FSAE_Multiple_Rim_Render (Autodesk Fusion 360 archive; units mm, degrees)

design "FSAE Multiple Rim Render" references "FSAE Rim"
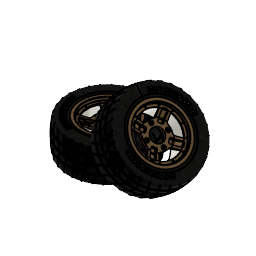
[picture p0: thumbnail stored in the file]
part number: 2026-08-31-14-58-38-211
component_insert "Component Insert1"
component_insert "Component Insert2"

design "FSAE Rim" references "Hexagon Nut DIN 934 - M4 x 0.7 Steel 6 Plain", "Hexagon Socket Head Cap Screw DIN 912 - M4 x 0.7 x 16 Steel 4.6 Plain"
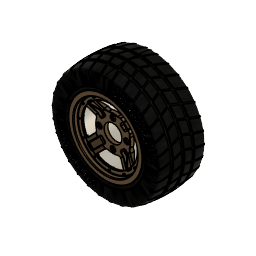
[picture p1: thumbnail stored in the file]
part number: 2026-07-27-09-56-27-671
part number: 2026-08-04-10-59-52-273
part number: 2026-08-04-10-59-52-284
part number: 2026-08-04-10-59-52-289
sketch "Sketch1" plane through (0, 0, 0) normal (1, 0, 0) x axis (0, 1, 0)
  line L1 (153.5, 0) -> (0, 0)
  line L2 (0, 119.5) -> (0, 104)
  line L3 (143.5, 124.5) -> (5, 124.5)
  line L4 (148.5, 134.75) -> (148.5, 129.5)
  line L5 (153.5, 138.25) -> (152, 138.25)
  line L6 (2.5, 119.5) -> (2.5, 104)
  line L7 (143.5, 122) -> (5, 122)
  line L8 (151, 134.75) -> (151, 129.5)
  line L9 (153.5, 135.75) -> (152, 135.75)
  line L10 (2.5, 104) -> (0, 104)
  line L11 (153.5, 135.75) -> (153.5, 138.25)
  arc A1 centre (152, 134.75) radius 3.5 clockwise from (148.5, 134.75) to (152, 138.25)
  arc A2 centre (143.5, 129.5) radius 5 clockwise from (148.5, 129.5) to (143.5, 124.5)
  arc A3 centre (5, 119.5) radius 5 clockwise from (0, 119.5) to (5, 124.5)
  arc A4 centre (5, 119.5) radius 2.5 clockwise from (2.5, 119.5) to (5, 122)
  arc A5 centre (143.5, 129.5) radius 7.5 clockwise from (151, 129.5) to (143.5, 122)
  arc A6 centre (152, 134.75) radius 1 clockwise from (151, 134.75) to (152, 135.75)
  point P1 (0, 0)
  point P2 (0, 0)
  point P4 (0, 104)
  point P3 (153.5, 0)
  point P7 (153.5, 138.25)
  point P6 (148.5, 124.5)
  point P5 (0, 124.5)
  coincident P1 P2
  horizontal L1
  perpendicular L1 L2
  perpendicular L2 L3
  perpendicular L3 L4
  perpendicular L4 L5
  vertical P1 P4
  vertical P3 P7
  tangent L4 A1
  tangent L5 A1
  coincident P6 L3
  coincident P6 L4
  tangent L3 A2
  tangent L4 A2
  coincident P5 L2
  coincident P5 L3
  tangent L2 A3
  tangent L3 A3
  equal A2 A3
  perpendicular L6 L10
  perpendicular L9 L11
  dimension "d1" distance P2 P3 = 153.5
  dimension "d2" = 208
  dimension "d3" = 249
  dimension "d4" = 276.5
  dimension "d5" distance P5 P6 = 148.5
  dimension "d6" radius A1 = 3.5
  dimension "d7" radius A2 = 5
  dimension "d8" = 2.5
revolve "Revolve1" sketch "Sketch1" AlongAngle 360 bodies "FSAE Rim Back"
sketch "Sketch2" plane through (0, 0, 0) normal (0, -1, 0) x axis (1, 0, 0)
  circle C1 centre (0, 0) radius 104
  circle C2 centre (0, 0) radius 119.5
  circle C3 centre (0, 0) radius 112
  circle C4 centre (0, 112) radius 2.15
  point P1 (0, 0)
  point P3 (0, 0)
  point P4 (0, 112)
  coincident P1 P3
  coincident C3 P4
  vertical P3 P4
  dimension "d10" diameter C3 = 224
  dimension "d11" diameter C4 = 4.3
extrude "Extrude1" cut sketch "Sketch2" profile of C4 to an object
circular_pattern "C-Pattern1" TotalAngle 360
canvas "Canvas1"
move "Move1"
sketch "Sketch4" plane through (0, 0, 0) normal (1, 0, 0) x axis (0, 1, 0)
  line L1 (14, 0) -> (0, 0)
  line L2 (14, 72.5) -> (14, 0)
  line L3 (-8, 102.5) -> (14, 72.5)
  line L4 (-8, 124.5) -> (-8, 102.5)
  line L5 (-23.5, 124.5) -> (-8, 124.5)
  line L6 (-23.5, 138) -> (-23.5, 124.5)
  line L7 (-28.25, 138) -> (-23.5, 138)
  line L8 (-28.25, 0) -> (-28.25, 138)
  line L9 (0, 0) -> (-28.25, 0)
  line L10 (-13, 118.1658) -> (-28.25, 119.5)
  line L11 (-13, 102.5) -> (-13, 118.1658)
  line L12 (0, 68.6338) -> (-13, 102.5)
  line L13 (0, 0) -> (0, 68.6338)
  point P1 (0, 0)
  point P2 (0, 0)
  point P11 (0, 0)
  point P12 (-28.25, 119.5)
  point P5 (-8, 102.5)
  point P14 (-13, 102.5)
  point P3 (14, 0)
  point P4 (14, 72.5)
  point P6 (-8, 124.5)
  point P8 (-23.5, 138)
  point P9 (-28.25, 138)
  coincident P1 P2
  horizontal L1
  perpendicular L1 L2
  perpendicular L1 L4
  perpendicular L4 L5
  perpendicular L5 L6
  perpendicular L6 L7
  coincident P1 P11
  collinear L1 L9
  perpendicular L8 L9
  coincident L8 P12
  parallel L8 L11
  vertical L13
  horizontal P5 P14
  dimension "d29" distance P2 P3 = 14
  dimension "d30" = 145
  dimension "d31" = 205
  dimension "d32" = 249
  dimension "d33" = 276
  dimension "d34" distance P4 P6 = 22
  dimension "d35" distance P6 P8 = 15.5
  dimension "d36" distance P8 P9 = 4.75
  dimension "d37" distance L4 L11 = 5
  dimension "d38" angle L12 L13 = 159
  dimension "d39" angle L10 L11 = 95
  dimension "d40" = 239
revolve "Revolve3" sketch "Sketch4" AlongAngle 360 bodies "FSAE Rim Front"
sketch "Sketch5" plane through (0, 0, 0) normal (0, -1, 0) x axis (1, 0, 0)
  circle C1 centre (0, 0) radius 68.6338
  circle C2 centre (0, 0) radius 33
  point P1 (0, 0)
  point P3 (0, 0)
  coincident P1 P3
  dimension "d42" diameter C2 = 66
extrude "Extrude2" cut sketch "Sketch5" profile of C2 to an object
sketch "Sketch6" plane through (0, 0, 0) normal (0, -1, 0) x axis (1, 0, 0)
  circle C1 centre (0, 0) radius 33
  circle C2 centre (0, 0) radius 68.6338
  circle C3 centre (0, 0) radius 50.8
  point P1 (0, 0)
  point P4 (0, 0)
  point P3 (0, 50.8)
  coincident P1 P4
  coincident P3 C3
  vertical P1 P3
  dimension "d45" diameter C3 = 101.6
hole "Hole1" HoleDiameter 10.5 TipAngle 180 CBDepth 5 CBDiameter 20
chamfer "Chamfer2" sketch "Sketch1" distance 0.5
circular_pattern "C-Pattern2" TotalAngle 360
sketch "Sketch7" plane through (0, -13, 0) normal (0, -1, 0) x axis (1, 0, 0)
  circle C1 centre (0, 0) radius 102.5
  circle C2 centre (0, 0) radius 118.1658
  circle C3 centre (0, 0) radius 112
  point P1 (0, 0)
  point P3 (0, 0)
  point P4 (0, 112)
  coincident P1 P3
  coincident C3 P4
  vertical P1 P4
  dimension "d53" diameter C3 = 224
hole "Hole2" HoleDiameter 4.3 TipAngle 180
circular_pattern "C-Pattern3" TotalAngle 360
fillet "Fillet1" radius 1 3 2
chamfer "Chamfer1" distance 0.5
form "Form1" bodies "Tire"
fillet "Fillet2" radius 5
sketch "Sketch8" plane through (0, 0, 0) normal (1, 0, 0) x axis (0, 1, 0)
  line L1 (47.5, 224.911) -> (47.5, 204.911)
  line L2 (57.5, 224.911) -> (47.5, 224.911)
  line L3 (57.5, 204.9943) -> (57.5, 224.911)
  line L4 (87.5, 224.911) -> (87.5, 204.2438)
  line L5 (97.5, 224.911) -> (87.5, 224.911)
  line L6 (97.5, 203.6595) -> (97.5, 224.911)
  line L7 (17.5, 224.911) -> (17.5, 203.6595)
  line L8 (7.5, 224.911) -> (17.5, 224.911)
  line L9 (7.5, 202.9073) -> (7.5, 224.911)
  arc A1 centre (57.5, -395.0057) radius 600 clockwise from (-46, 196) to (161, 196)
  point P2 (-46, 196)
  point P3 (161, 196)
  point P8 (57.5, 204.9943)
  point P9 (87.5, 204.2438)
  point P12 (97.5, 203.6595)
  point P13 (17.5, 203.6595)
  point P16 (7.5, 202.9073)
  point P5 (47.5, 204.911)
  point P1 (0, 0)
  point P6 (47.5, 224.911)
  point P7 (57.5, 224.911)
  horizontal P2 P3
  vertical L1
  perpendicular L1 L2
  midpoint A1 P8
  perpendicular L2 L3
  coincident A1 P9
  parallel L3 L4
  perpendicular L4 L5
  coincident A1 P12
  perpendicular L5 L6
  coincident A1 P13
  perpendicular L5 L7
  perpendicular L7 L8
  coincident A1 P16
  perpendicular L8 L9
  collinear L2 L8
  collinear L2 L5
  equal L2 L8
  equal L2 L5
  coincident A1 P5
  dimension "d68" radius A1 = 600
  dimension "d69" distance P1 P3 = 196
  dimension "d70" distance P1 P2 = 46
  dimension "d71" distance P1 P3 = 161
  dimension "d73" distance P6 P7 = 10
  dimension "d74" distance L1 L7 = 30
  dimension "d75" distance L3 L4 = 30
  dimension "d76" distance P5 P6 = 20
revolve "Revolve4" AlongAngle 360
revolve "Revolve5" sketch "Sketch8" AlongAngle 360
work_plane "WorkPlane1" AlongDistance 275 ExtraOffset 0
sketch "Sketch9" plane through (0, 0, 275) normal (0, 0, 1) x axis (1, 0, 0)
  line L1 (-48.7008, 53.5011) -> (0, -75.7953)
  line L2 (0, 197.5142) -> (-48.7008, 53.5011)
  line L3 (-43.392, 53.5917) -> (4.6791, -74.0329)
  line L4 (4.7365, 195.9124) -> (-43.392, 53.5917)
  line L5 (4.6791, -74.0329) -> (0, -75.7953)
  line L6 (0, 197.5142) -> (4.7365, 195.9124)
  perpendicular L3 L5
  perpendicular L2 L6
  dimension "d80" = 5
step "SurfaceExtend" extendDistance 125
extrude "Extrude3" cut sketch "Sketch9" to an object
circular_pattern "C-Pattern4" countU 30 TotalAngle 360
remove_body "RemoveBody1"
remove_body "RemoveBody2"
work_plane "WorkPlane2" AlongDistance -150 ExtraOffset 0
sketch "Sketch10" plane through (0, -150, 0) normal (0, 1, 0) x axis (1, 0, 0)
  circle C1 centre (0, 0) radius 157.5
  point P1 (0, 0)
  point P2 (0, 0)
  coincident P1 P2
  dimension "d88" diameter C1 = 315
  dimension "d89" Text1-Height = 20
extrude "Extrude4" sketch "Sketch10" blind 2
circular_pattern "C-Pattern5" TotalAngle 360
component_from_bodies "Body->Comp1"
component_from_bodies "Body->Comp2"
component_from_bodies "Body->Comp3"
sketch "Sketch1" plane through (0, -13, 0) normal (0, -1, 0) x axis (1, 0, 0)
  line L1 (0, 103.056) -> (0, 0)
  line L2 (103.056, 0) -> (0, 0)
  line L3 (72.8716, 72.8716) -> (0, 0)
  line L4 (88.3726, 53.0172) -> (60.1041, 24.7487)
  line L5 (53.0172, 88.3726) -> (24.7487, 60.1041)
  circle C1 centre (0, 0) radius 103.056
  circle C2 centre (0, 112) radius 2.15
  circle C3 centre (56, 96.9948) radius 2.15
  circle C4 centre (96.9948, 56) radius 2.15
  circle C5 centre (112, 0) radius 2.15
  circle C6 centre (96.9948, -56) radius 2.15
  circle C7 centre (56, -96.9948) radius 2.15
  circle C8 centre (0, -112) radius 2.15
  circle C9 centre (-56, -96.9948) radius 2.15
  circle C10 centre (-96.9948, -56) radius 2.15
  circle C11 centre (-112, 0) radius 2.15
  circle C12 centre (-96.9948, 56) radius 2.15
  circle C13 centre (-56, 96.9948) radius 2.15
  circle C14 centre (0, 0) radius 116.3331
  arc A1 centre (0, 0) radius 65 clockwise from (0, 65) to (65, 0)
  arc A2 centre (0, 0) radius 65 clockwise from (65, 0) to (0, 65)
  point P2 (0, 0)
  point P16 (0, 0)
  point P17 (0, 103.056)
  point P18 (103.056, 0)
  point P15 (0, 0)
  point P19 (0, 0)
  point P20 (72.8716, 72.8716)
  point P22 (24.7487, 60.1041)
  point P21 (60.1041, 24.7487)
  point P23 (53.0172, 88.3726)
  point P24 (88.3726, 53.0172)
  point P25 (0, 65)
  point P26 (65, 0)
  concentric C1 A1
  coincident P2 P16
  coincident C1 P17
  vertical L1
  coincident C1 P18
  perpendicular L1 L2
  coincident P15 P19
  coincident C1 P20
  coincident P22 A1
  coincident P21 A1
  coincident C1 P23
  coincident C1 P24
  coincident L1 P25
  coincident L2 P26
  concentric A1 A2
  dimension "d95" diameter A1 = 130
  dimension "d96" angle L1 L3 = 45
extrude "Extrude1" cut sketch "Sketch1" profile of C1 L1 L2 L4 L5 A1 to an object
circular_pattern "C-Pattern1" TotalAngle 360
sketch "Sketch2" plane through (0, -13, 0) normal (0, -1, 0) x axis (1, 0, 0)
  line L1 (72.8716, 72.8716) -> (0, 0)
  line L2 (65.9862, 82.9568) -> (25.8367, 42.8073)
  line L3 (82.9568, 65.9862) -> (42.8073, 25.8367)
  arc A1 centre (0, 0) radius 103.056 clockwise from (-53.0172, 88.3726) to (53.0172, 88.3726)
  arc A2 centre (0, 0) radius 103.056 clockwise from (53.0172, 88.3726) to (88.3726, 53.0172)
  arc A3 centre (0, 0) radius 103.056 clockwise from (88.3726, 53.0172) to (88.3726, -53.0172)
  arc A4 centre (0, 0) radius 103.056 clockwise from (88.3726, -53.0172) to (53.0172, -88.3726)
  arc A5 centre (0, 0) radius 103.056 clockwise from (53.0172, -88.3726) to (-53.0172, -88.3726)
  arc A6 centre (0, 0) radius 103.056 clockwise from (-53.0172, -88.3726) to (-88.3726, -53.0172)
  arc A7 centre (0, 0) radius 103.056 clockwise from (-88.3726, -53.0172) to (-88.3726, 53.0172)
  arc A8 centre (0, 0) radius 103.056 clockwise from (-88.3726, 53.0172) to (-53.0172, 88.3726)
  circle C1 centre (0, 112) radius 2.15
  circle C2 centre (56, 96.9948) radius 2.15
  circle C3 centre (96.9948, 56) radius 2.15
  circle C4 centre (112, 0) radius 2.15
  circle C5 centre (96.9948, -56) radius 2.15
  circle C6 centre (56, -96.9948) radius 2.15
  circle C7 centre (0, -112) radius 2.15
  circle C8 centre (-56, -96.9948) radius 2.15
  circle C9 centre (-96.9948, -56) radius 2.15
  circle C10 centre (-112, 0) radius 2.15
  circle C11 centre (-96.9948, 56) radius 2.15
  circle C12 centre (-56, 96.9948) radius 2.15
  circle C13 centre (0, 0) radius 116.3331
  circle C14 centre (0, 0) radius 50
  circle C15 centre (0, 0) radius 106
  point P23 (0, 0)
  point P25 (0, 0)
  point P27 (25.8367, 42.8073)
  point P28 (42.8073, 25.8367)
  point P29 (82.9568, 65.9862)
  point P30 (65.9862, 82.9568)
  parallel L1 L2
  parallel L1 L3
  coincident P23 P25
  concentric C14 C15
  coincident C14 P27
  coincident C14 P28
  coincident C15 P29
  coincident C15 P30
  dimension "d103" distance L1 L2 = 12
  dimension "d104" distance L1 L3 = 12 (= "d103")
  dimension "d105" diameter C14 = 100
  dimension "d106" diameter C15 = 212
extrude "Extrude2" cut sketch "Sketch2" profile of A2 L2 L3 C14 C15 to an object offset 2
fillet "Fillet1" radius 5
fillet "Fillet2" radius 10
fillet "Fillet3" radius 2
circular_pattern "C-Pattern2" TotalAngle 360
fillet "Fillet4" radius 15 5
chamfer "Chamfer1" sketch "Sketch1" distance 1
step "Screw1"
joint "Assemble" alignAngle 0 alignOffsetX 0 alignOffsetY 0 alignOffsetZ 0
step "Screw2"
joint "Assemble" alignAngle 0 alignOffsetX 0 alignOffsetY 0 alignOffsetZ 0
step "Screw3"
joint "Assemble" alignAngle 0 alignOffsetX 0 alignOffsetY 0 alignOffsetZ 0
step "Screw4"
joint "Assemble" alignAngle 0 alignOffsetX 0 alignOffsetY 0 alignOffsetZ 0
step "Screw5"
joint "Assemble" alignAngle 0 alignOffsetX 0 alignOffsetY 0 alignOffsetZ 0
step "Screw6"
joint "Assemble" alignAngle 0 alignOffsetX 0 alignOffsetY 0 alignOffsetZ 0
step "Screw7"
joint "Assemble" alignAngle 0 alignOffsetX 0 alignOffsetY 0 alignOffsetZ 0
step "Screw8"
joint "Assemble" alignAngle 0 alignOffsetX 0 alignOffsetY 0 alignOffsetZ 0
step "Screw9"
joint "Assemble" alignAngle 0 alignOffsetX 0 alignOffsetY 0 alignOffsetZ 0
step "Screw10"
joint "Assemble" alignAngle 0 alignOffsetX 0 alignOffsetY 0 alignOffsetZ 0
step "Screw11"
joint "Assemble" alignAngle 0 alignOffsetX 0 alignOffsetY 0 alignOffsetZ 0
step "Screw12"
joint "Assemble" alignAngle 0 alignOffsetX 0 alignOffsetY 0 alignOffsetZ 0
step "Nut13"
joint "Assemble" alignAngle 0 alignOffsetX 0 alignOffsetY 0 alignOffsetZ 0
step "Nut14"
joint "Assemble" alignAngle 0 alignOffsetX 0 alignOffsetY 0 alignOffsetZ 0
step "Nut15"
joint "Assemble" alignAngle 0 alignOffsetX 0 alignOffsetY 0 alignOffsetZ 0
step "Nut16"
joint "Assemble" alignAngle 0 alignOffsetX 0 alignOffsetY 0 alignOffsetZ 0
step "Nut17"
joint "Assemble" alignAngle 0 alignOffsetX 0 alignOffsetY 0 alignOffsetZ 0
step "Nut18"
joint "Assemble" alignAngle 0 alignOffsetX 0 alignOffsetY 0 alignOffsetZ 0
step "Nut19"
joint "Assemble" alignAngle 0 alignOffsetX 0 alignOffsetY 0 alignOffsetZ 0
step "Nut20"
joint "Assemble" alignAngle 0 alignOffsetX 0 alignOffsetY 0 alignOffsetZ 0
step "Nut21"
joint "Assemble" alignAngle 0 alignOffsetX 0 alignOffsetY 0 alignOffsetZ 0
step "Nut22"
joint "Assemble" alignAngle 0 alignOffsetX 0 alignOffsetY 0 alignOffsetZ 0
step "Nut23"
joint "Assemble" alignAngle 0 alignOffsetX 0 alignOffsetY 0 alignOffsetZ 0
step "Nut24"
joint "Assemble" alignAngle 0 alignOffsetX 0 alignOffsetY 0 alignOffsetZ 0
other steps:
base_feature "Base Feature1" bodies "FSAE Rim Back"
base_feature "Base Feature1" bodies "Tire"
base_feature "Base Feature1" bodies "FSAE Rim Front"
create_component "CreateComponent1"
reparent_decal "ReparentDecal1"
remove_body "RemoveBody3"
create_component "CreateComponent2"
reparent_decal "ReparentDecal2"
remove_body "RemoveBody4"
create_component "CreateComponent3"
reparent_decal "ReparentDecal3"
remove_body "RemoveBody5"
joint_origin "JointOrigin1"
joint_origin "JointOrigin2"
joint_origin "JointOrigin3"
joint_origin "JointOrigin4"
joint_origin "JointOrigin5"
joint_origin "JointOrigin6"
joint_origin "JointOrigin7"
joint_origin "JointOrigin8"
joint_origin "JointOrigin9"
joint_origin "JointOrigin10"
joint_origin "JointOrigin11"
joint_origin "JointOrigin12"
joint_origin "JointOrigin1"
joint_origin "JointOrigin2"
joint_origin "JointOrigin3"
joint_origin "JointOrigin4"
joint_origin "JointOrigin5"
joint_origin "JointOrigin6"
joint_origin "JointOrigin7"
joint_origin "JointOrigin8"
joint_origin "JointOrigin9"
joint_origin "JointOrigin10"
joint_origin "JointOrigin11"
joint_origin "JointOrigin12"
named bodies: "FSAE Rim Back", "FSAE Rim Front", "Tire"

design "Hexagon Socket Head Cap Screw DIN 912 - M4 x 0.7 x 16 Steel 4.6 Plain"
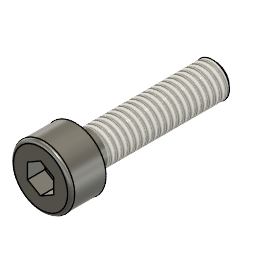
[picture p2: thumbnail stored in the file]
description: Hexagon Socket Head Cap Screw DIN 912 - M4 x 0.7 x 16
part number: DIN 912 - M4 x 0.7 x 16 Steel 4.6 Plain
parameter "adsk_nomlen" = 16
parameter "adsk_headh" = 4
parameter "adsk_headdia" = 7
parameter "adsk_nomdia" = 4
parameter "adsk_philwidth" = 3
parameter "adsk_phildepth" = 2
parameter "adsk_thrlen" = 14.25
parameter "adsk_startlen" = 0.4294
parameter "adsk_endpointdia" = 3.1412
sketch "Sketch1" plane through (0, 0, 0) normal (0, 1, 0) x axis (1, 0, 0)
  line L1 (-2, 16) -> (-2, 0)
  line L2 (0, 16) -> (-2, 16)
  line L3 (0, -4) -> (0, 16)
  line L4 (-3.5, 0) -> (-2, 0)
  line L5 (-3.5, -4) -> (-3.5, 0)
  line L6 (0, -4) -> (-3.5, -4)
  point P1 (0, 0)
  point P4 (0, 16)
  point P7 (0, -4)
  point P5 (-3.5, 0)
  perpendicular L1 L2
  collinear P1 P4 P7
  perpendicular L1 L4
  coincident P1 L4
  vertical L3
  coincident L3 P7
  perpendicular L3 L6
  dimension "d101" distance P1 L2 = 16 (= "adsk_nomlen")
  dimension "d102" distance P5 L6 = 4 (= "adsk_headh")
  dimension "d109" = 7 (= "adsk_headdia")
  dimension "d110" = 4 (= "adsk_nomdia")
revolve "Revolve1" sketch "Sketch1" AlongAngle 360
work_plane "WorkPlane1" AlongDistance 4 (= "adsk_headh")
sketch "Sketch6" plane through (0, 0, 4) normal (0, 0, 1) x axis (1, 0, 0)
  line L1 (1.5, -0.866) -> (0, -1.7321)
  line L2 (1.5, 0.866) -> (1.5, -0.866)
  line L3 (0, 1.7321) -> (1.5, 0.866)
  line L4 (-1.5, 0.866) -> (0, 1.7321)
  line L5 (-1.5, -0.866) -> (-1.5, 0.866)
  line L6 (0, -1.7321) -> (-1.5, -0.866)
  point P1 (0, 0)
  point P8 (0, 0)
  coincident P1 P8
  vertical L2
  dimension "d111" distance L2 L5 = 3 (= "adsk_philwidth")
extrude "Extrude1" cut sketch "Sketch6" no distance stored
extrude "Extrude2" cut of existing geometry no distance stored taper -85
thread "Thread3" ThreadOffset 0 ThreadLength 14.25 (= "min(adsk_thrlen; adsk_nomlen - 0.001 mm)")
fillet "Fillet4" radius 0.4 (= "adsk_nomdia * 0.1")
sketch "Sketch7" plane through (0, 0, 0) normal (0, 1, 0) x axis (1, 0, 0)
  line L1 (-2.04, 15.5706) -> (-2.04, 16)
  line L2 (-1.5706, 16) -> (-2.04, 15.5706)
  line L3 (0, -4) -> (0, 16)
  line L4 (0, 16) -> (-2.04, 16)
  point P5 (0, 16)
  point P7 (0, 16)
  point P4 (-1.5706, 16)
  point P3 (-2.04, 15.5706)
  coincident P5 P7
  perpendicular L3 L4
  coincident P4 L4
  perpendicular L1 L4
  dimension "d104" distance P4 L3 = 1.5706 (= "adsk_endpointdia / 2")
  dimension "d105" distance L1 P7 = 2.04 (= "adsk_nomdia * 0.51")
  dimension "d106" distance P3 L4 = 0.4294 (= "adsk_startlen")
revolve "Revolve3" sketch "Sketch7" AlongAngle 360
joint_origin "JointOrigin2" OffsetX 0 OffsetY 0 OffsetZ 0 AngleZ 0

design "Hexagon Nut DIN 934 - M4 x 0.7 Steel 6 Plain"
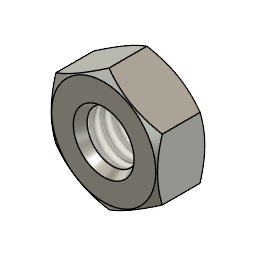
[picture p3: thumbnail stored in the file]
description: Hexagon Nut DIN 934 - M4 x 0.7
part number: DIN 934 - M4 x 0.7 Steel 6 Plain
parameter "adsk_nheig" = 3.2
parameter "adsk_maxdia" = 8.085
parameter "adsk_nomdia" = 4
parameter "adsk_waflat" = 7
parameter "adsk_chamang1" = 30
parameter "adsk_chamang2" = 30
parameter "adsk_beardia" = 6.86 (= "adsk_waflat * 0.98")
sketch "Sketch1" plane through (0, 0, 0) normal (0, 1, 0) x axis (1, 0, 0)
  line L1 (0, -3.2) -> (0, 0)
  line L2 (-3.43, 0) -> (-2, 0)
  line L3 (-4.0425, -0.3536) -> (-3.43, 0)
  line L4 (-4.0425, -2.8464) -> (-4.0425, -0.3536)
  line L5 (-3.43, -3.2) -> (-4.0425, -2.8464)
  line L6 (-2, -3.2) -> (-3.43, -3.2)
  line L7 (-2, 0) -> (-2, -3.2)
  point P3 (0, -3.2)
  point P1 (0, 0)
  point P2 (0, 0)
  point P10 (0, 0)
  point P5 (-3.43, 0)
  point P8 (-3.43, -3.2)
  vertical L1
  coincident L1 P3
  coincident P1 L1
  horizontal L2
  coincident P1 L2
  coincident P2 P10
  coincident P3 L6
  vertical P5 P8
  dimension "d121" = 4 (= "adsk_nomdia")
  dimension "d122" angle L2 L3 = 30 (= "adsk_chamang1")
  dimension "d123" angle L5 L6 = 30 (= "adsk_chamang2")
  dimension "d128" = 8.085 (= "adsk_maxdia")
  dimension "d172" = 6.86 (= "adsk_beardia")
  dimension "d179" distance L2 L6 = 3.2 (= "adsk_nheig")
revolve "Revolve1" sketch "Sketch1" AlongAngle 360
sketch "Sketch8" plane through (0, 0, 3.2) normal (0, 0, 1) x axis (1, 0, 0)
  line L1 (-3.5, 2.0228) -> (-3.5, -2.0228)
  circle C1 centre (0, 0) radius 2
  circle C2 centre (0, 0) radius 4.0425
  point P3 (-3.5, 2.0228)
  point P2 (-3.5, -2.0228)
  point P1 (0, 0)
  coincident P3 C2
  coincident P2 C2
  vertical L1
  dimension "d114" distance P1 L1 = 3.5 (= "adsk_waflat / 2")
extrude "Extrude5" cut sketch "Sketch8" profile of L1 C2 no distance stored
circular_pattern "C-Pattern2" TotalAngle 360
thread "Thread3" ThreadOffset 0 ThreadLength 10
sketch "Sketch12" plane through (0, 0, 0) normal (0, 1, 0) x axis (1, 0, 0)
  line L1 (0, 0) -> (-2, 0)
  line L2 (-2, 0) -> (-1.0762, -1.6)
  line L3 (0, -3.2) -> (-2, -3.2)
  line L4 (-2, -3.2) -> (-1.0762, -1.6)
  line L5 (0, -3.2) -> (0, 0)
  point P4 (-1.0762, -1.6)
  point P7 (-1.0762, -1.6)
  point P2 (-2, 0)
  point P5 (-2, -3.2)
  point P6 (0, -3.2)
  point P9 (0, -3.2)
  point P1 (0, 0)
  point P3 (0, 0)
  horizontal L1
  coincident P4 P7
  vertical P2 P5
  coincident P6 P9
  coincident P1 P3
  perpendicular L3 L5
  dimension "d169" angle L3 L4 = 60
  dimension "d177" distance P2 L5 = 2 (= "adsk_nomdia * 0.5")
  dimension "d178" angle L1 L2 = 60
revolve "Revolve3" sketch "Sketch12" AlongAngle 360
joint_origin "JointOrigin9" OffsetX 0 OffsetY 0 OffsetZ 0 AngleZ 0
joint_origin "JointOrigin10" OffsetX 0 OffsetY 0 OffsetZ 3.2 (= "adsk_nheig") AngleZ 0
